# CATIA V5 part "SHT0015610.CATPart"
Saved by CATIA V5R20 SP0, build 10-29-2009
Part number: SHT0015610
Source: Unknown
Bounding box of the stored display mesh (mm): x 524.613 to 655.277, y -359.501 to -344.5, z -273.191 to -67.827
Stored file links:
  D:\Program Files\feiq\AutoRecv Files\李宁-设计公司(186024940125)\2023-02-27 13_19_18\右下连接板总成\SHT0015610.CATPart
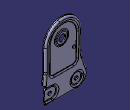
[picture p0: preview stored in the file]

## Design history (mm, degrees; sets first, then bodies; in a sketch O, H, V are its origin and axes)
Body1 "0" (main body)
Body2 "SHT0015431右下连接板"
  Solid1: solid without history
Body3 "BFA0000388盘簧钩销"
  Solid2: solid without history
